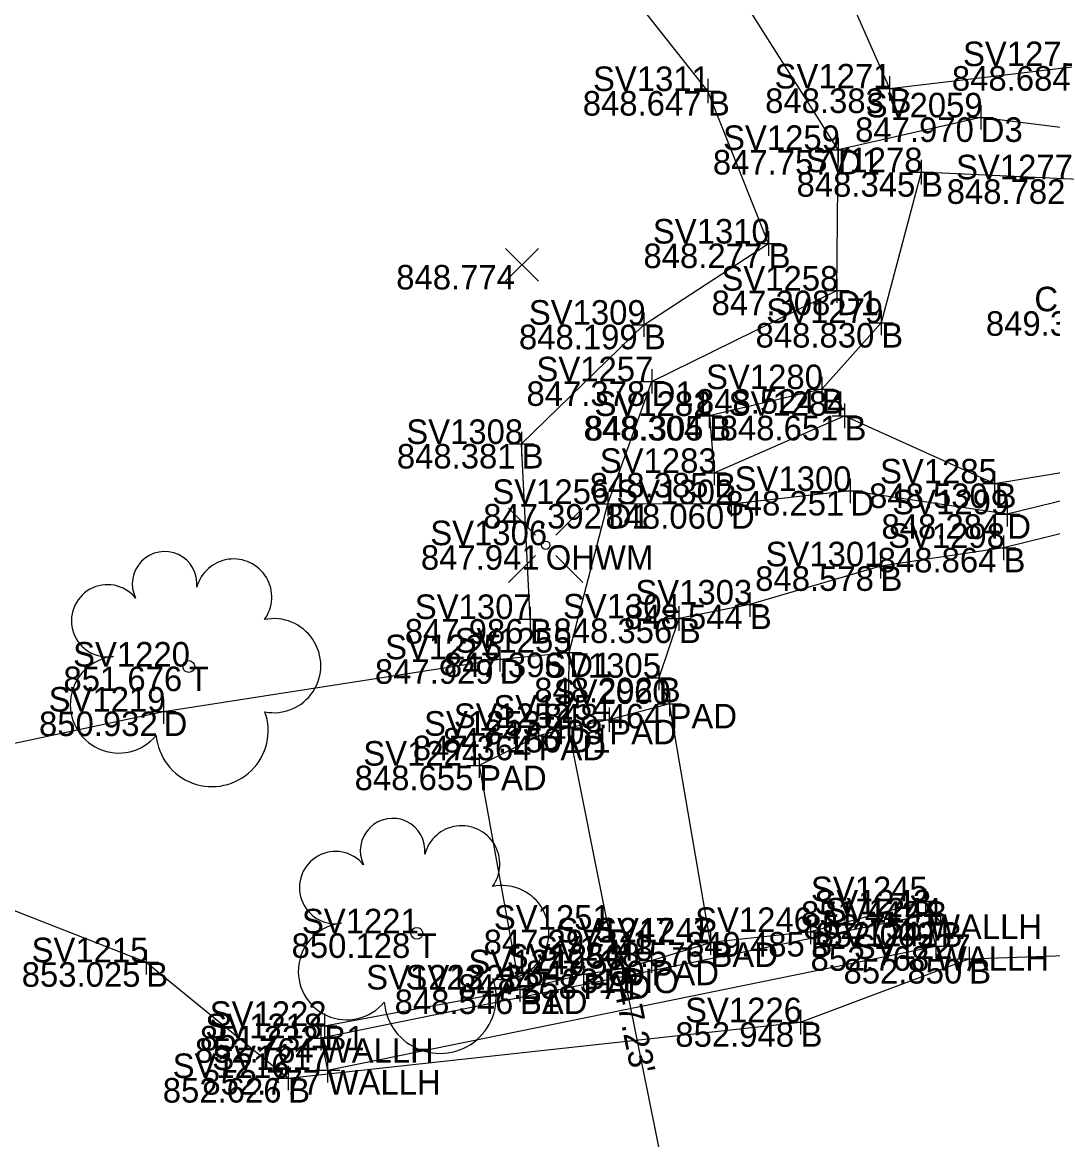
# Model space of a CAD drawing. Extents: x 2125299 to 2129212, y 713100 to 714300.
# Drawn here: x 2128258.44 to 2128300.4, y 714146.02 to 714191.52 of the extents above; entities that cross this region are included whole.
import ezdxf

# ---------------------------------------------------------------- set-up
doc = ezdxf.new("R2010")
doc.units = 0
for name, color, linetype in [('DR_X_Ditch', 7, 'Continuous'), ('DR_X_Headwall', 7, 'Continuous'), ('DR_X_Storm_Sewer', 7, 'Continuous'), ('RD_X_Concrete_Pad', 7, 'Continuous'), ('RW_P_Esmt_TMP', 7, 'Continuous'), ('RW_X_CL_100_Cardinal_Points', 7, 'Continuous'), ('RW_X_CL_100_Stations', 7, 'Continuous'), ('RW_X_Esmt_CH', 7, 'Continuous'), ('RW_X_Fee_WL', 7, 'Continuous'), ('SC_Scratch1', 7, 'Continuous'), ('SV_X_Break_Lines', 7, 'Continuous'), ('SV_X_Mon_Cells_Found', 7, 'Continuous'), ('SV_X_Text_Elevation', 7, 'Continuous'), ('SV_X_Text_Name', 7, 'Continuous')]:
    doc.layers.add(name, color=color, linetype=linetype)

msp = doc.modelspace()

# ---------------------------------------------------------------- linework, layer by layer
at = {"layer": 'DR_X_Ditch'}
for points in [[(2128282.878, 714152.985), (2128282.322, 714154.568), (2128280.684, 714162.784), (2128280.715, 714165.854), (2128282.282, 714171.907), (2128284.07, 714176.901), (2128291.608, 714180.596), (2128291.656, 714186.324), (2128287.057, 714193.601), (2128283.052, 714208.887), (2128284.129, 714216.499), (2128286.829, 714221.225)], [(2128315.102, 714185.935), (2128305.895, 714186.59), (2128297.467, 714187.651), (2128291.656, 714186.324)], [(2128404.428, 714186.272), (2128369.06, 714182.378), (2128353.253, 714176.31), (2128345.761, 714173.482), (2128342.574, 714173.517), (2128335.146, 714174.466), (2128320.718, 714174.933), (2128310.69, 714174.47), (2128298.547, 714171.487), (2128292.157, 714172.437), (2128287.299, 714171.899), (2128282.282, 714171.907)], [(2128126.019, 714119.425), (2128165.524, 714127.077), (2128190.466, 714132.501), (2128226.541, 714148.801), (2128253.762, 714161.242), (2128264.195, 714163.453), (2128277.883, 714165.583), (2128280.715, 714165.854)]]:
    msp.add_lwpolyline(points, dxfattribs=at)
at = {"layer": 'DR_X_Headwall'}
msp.add_lwpolyline([(2128270.591, 714150.148), (2128270.869, 714148.851), (2128295.638, 714153.894), (2128295.357, 714155.189)], close=True, dxfattribs=at)
at = {"layer": 'DR_X_Storm_Sewer'}
msp.add_line((2128282.878, 714152.985), (2128337.681, 713883.118), dxfattribs=at)
at = {"layer": 'RD_X_Concrete_Pad'}
msp.add_lwpolyline([(2128284.794, 714163.766), (2128282.342, 714163.12), (2128280.684, 714162.784), (2128279.461, 714162.469), (2128277.044, 714161.25), (2128278.705, 714152.132), (2128281.29, 714152.752), (2128282.878, 714152.985), (2128284.06, 714153.308), (2128286.462, 714154.049)], close=True, dxfattribs=at)
at = {"layer": 'RW_X_CL_100_Cardinal_Points'}
for p, q in [((2128282.878, 714153.485), (2128282.878, 714152.485)), ((2128282.378, 714152.985), (2128283.378, 714152.985)), ((2128282.878, 714152.985), (2128282.878, 714152.985))]:
    msp.add_line(p, q, dxfattribs=at)
at = {"layer": 'RW_X_CL_100_Stations'}
for centre in [(2128265.221, 714165.285), (2128274.506, 714154.419)]:
    msp.add_circle(centre, 0.24, dxfattribs=at)
for centre, radius, start, end in [((2128264.237, 714168.653), 1.317, 354.0047, 205.9741), ((2128267.047, 714168.114), 1.553, 323.83, 165.0376), ((2128261.912, 714167.149), 1.471, 39.0625, 279.5412), ((2128268.681, 714165.321), 1.915, 259.1453, 101.4596), ((2128262.368, 714163.737), 1.974, 96.1722, 320.5737), ((2128266.167, 714162.68), 2.284, 184.9476, 19.4572), ((2128273.522, 714157.786), 1.317, 354.0047, 205.9741), ((2128276.332, 714157.248), 1.553, 323.83, 165.0376), ((2128271.197, 714156.283), 1.471, 39.0625, 279.5412), ((2128277.966, 714154.454), 1.915, 259.1453, 101.4596), ((2128271.653, 714152.87), 1.974, 96.1722, 320.5737), ((2128275.452, 714151.813), 2.284, 184.9476, 19.4572)]:
    msp.add_arc(centre, radius, start, end, dxfattribs=at)
at = {"layer": 'SV_X_Break_Lines'}
for p, q in [((2128286.358, 714188.724), (2128286.358, 714188.724)), ((2128288.829, 714182.513), (2128288.829, 714182.513)), ((2128283.748, 714179.208), (2128283.748, 714179.208)), ((2128278.774, 714174.351), (2128278.774, 714174.351)), ((2128279.118, 714167.221), (2128279.118, 714167.221))]:
    msp.add_line(p, q, dxfattribs=at)
for points in [[(2128294.731, 714221.25), (2128286.429, 714216.107), (2128286.307, 714216.085), (2128290.211, 714206.434), (2128289.886, 714198.061), (2128291.79, 714193.305), (2128293.753, 714188.829), (2128301.414, 714189.738), (2128311.099, 714187.98), (2128315.392, 714186.993), (2128315.738, 714184.367), (2128308.586, 714184.286), (2128301.154, 714185.129), (2128295.038, 714185.419), (2128293.414, 714179.277), (2128290.994, 714176.583), (2128286.414, 714175.49), (2128286.417, 714175.493), (2128286.617, 714173.173), (2128291.92, 714175.499), (2128298.034, 714172.742), (2128324.661, 714177.129), (2128340.162, 714175.773), (2128345.323, 714175.683)], [(2128279.118, 714167.221), (2128278.774, 714174.351), (2128283.748, 714179.208), (2128288.829, 714182.513), (2128286.358, 714188.724), (2128281.871, 714194.398)], [(2128257.59, 714155.557), (2128263.487, 714153.243), (2128269.265, 714148.527), (2128290.131, 714150.799), (2128296.994, 714153.375), (2128311.857, 714153.897), (2128347.24, 714163.065), (2128380.908, 714169.426), (2128405.403, 714183.348)], [(2128342.539, 714171.803), (2128334.728, 714172.648), (2128320.995, 714173.612), (2128310.963, 714173.215), (2128298.394, 714170.12), (2128293.384, 714169.367), (2128288.065, 714167.811), (2128285.175, 714167.243), (2128284.357, 714164.829), (2128284.794, 714163.766)], [(2128295.832, 714154.861), (2128295.22, 714155.73), (2128290.538, 714154.475), (2128286.462, 714154.049)], [(2128270.743, 714150.65), (2128278.705, 714152.132)]]:
    msp.add_lwpolyline(points, dxfattribs=at)
at = {"layer": 'SV_X_Mon_Cells_Found'}
for p, q in [((2128286.358, 714189.224), (2128286.358, 714188.224)), ((2128293.753, 714189.329), (2128293.753, 714188.329)), ((2128285.858, 714188.724), (2128286.858, 714188.724)), ((2128286.358, 714188.724), (2128286.358, 714188.724)), ((2128293.253, 714188.829), (2128294.253, 714188.829)), ((2128293.753, 714188.829), (2128293.753, 714188.829)), ((2128297.467, 714188.151), (2128297.467, 714187.151)), ((2128296.967, 714187.651), (2128297.967, 714187.651)), ((2128297.467, 714187.651), (2128297.467, 714187.651)), ((2128291.656, 714186.824), (2128291.656, 714185.824)), ((2128291.156, 714186.324), (2128292.156, 714186.324)), ((2128291.656, 714186.324), (2128291.656, 714186.324)), ((2128295.038, 714185.919), (2128295.038, 714184.919)), ((2128294.538, 714185.419), (2128295.538, 714185.419)), ((2128295.038, 714185.419), (2128295.038, 714185.419)), ((2128288.829, 714183.013), (2128288.829, 714182.013)), ((2128288.329, 714182.513), (2128289.329, 714182.513)), ((2128288.829, 714182.513), (2128288.829, 714182.513)), ((2128291.608, 714181.096), (2128291.608, 714180.096)), ((2128291.108, 714180.596), (2128292.108, 714180.596)), ((2128291.608, 714180.596), (2128291.608, 714180.596)), ((2128283.748, 714179.708), (2128283.748, 714178.708)), ((2128293.414, 714179.777), (2128293.414, 714178.777)), ((2128283.248, 714179.208), (2128284.248, 714179.208)), ((2128283.748, 714179.208), (2128283.748, 714179.208)), ((2128292.914, 714179.277), (2128293.914, 714179.277)), ((2128293.414, 714179.277), (2128293.414, 714179.277)), ((2128284.07, 714177.401), (2128284.07, 714176.401)), ((2128283.57, 714176.901), (2128284.57, 714176.901)), ((2128284.07, 714176.901), (2128284.07, 714176.901)), ((2128290.994, 714177.083), (2128290.994, 714176.083)), ((2128290.494, 714176.583), (2128291.494, 714176.583)), ((2128290.994, 714176.583), (2128290.994, 714176.583)), ((2128286.414, 714175.99), (2128286.414, 714174.99)), ((2128286.417, 714175.993), (2128286.417, 714174.993)), ((2128291.92, 714175.999), (2128291.92, 714174.999)), ((2128285.914, 714175.49), (2128286.914, 714175.49)), ((2128285.917, 714175.493), (2128286.917, 714175.493)), ((2128286.414, 714175.49), (2128286.414, 714175.49)), ((2128286.417, 714175.493), (2128286.417, 714175.493)), ((2128291.42, 714175.499), (2128292.42, 714175.499)), ((2128291.92, 714175.499), (2128291.92, 714175.499)), ((2128278.774, 714174.851), (2128278.774, 714173.851)), ((2128278.274, 714174.351), (2128279.274, 714174.351)), ((2128278.774, 714174.351), (2128278.774, 714174.351)), ((2128286.617, 714173.673), (2128286.617, 714172.673)), ((2128286.117, 714173.173), (2128287.117, 714173.173)), ((2128286.617, 714173.173), (2128286.617, 714173.173)), ((2128298.034, 714173.242), (2128298.034, 714172.242)), ((2128292.157, 714172.937), (2128292.157, 714171.937)), ((2128297.534, 714172.742), (2128298.534, 714172.742)), ((2128298.034, 714172.742), (2128298.034, 714172.742)), ((2128282.282, 714172.407), (2128282.282, 714171.407)), ((2128287.299, 714172.399), (2128287.299, 714171.399)), ((2128291.657, 714172.437), (2128292.657, 714172.437)), ((2128292.157, 714172.437), (2128292.157, 714172.437)), ((2128281.782, 714171.907), (2128282.782, 714171.907)), ((2128282.282, 714171.907), (2128282.282, 714171.907)), ((2128286.799, 714171.899), (2128287.799, 714171.899)), ((2128287.299, 714171.899), (2128287.299, 714171.899)), ((2128298.547, 714171.987), (2128298.547, 714170.987)), ((2128298.047, 714171.487), (2128299.047, 714171.487)), ((2128298.547, 714171.487), (2128298.547, 714171.487)), ((2128298.394, 714170.62), (2128298.394, 714169.62)), ((2128297.894, 714170.12), (2128298.894, 714170.12)), ((2128298.394, 714170.12), (2128298.394, 714170.12)), ((2128293.384, 714169.867), (2128293.384, 714168.867)), ((2128292.884, 714169.367), (2128293.884, 714169.367)), ((2128293.384, 714169.367), (2128293.384, 714169.367)), ((2128288.065, 714168.311), (2128288.065, 714167.311)), ((2128279.118, 714167.721), (2128279.118, 714166.721)), ((2128285.175, 714167.743), (2128285.175, 714166.743)), ((2128287.565, 714167.811), (2128288.565, 714167.811)), ((2128288.065, 714167.811), (2128288.065, 714167.811)), ((2128284.675, 714167.243), (2128285.675, 714167.243)), ((2128285.175, 714167.243), (2128285.175, 714167.243)), ((2128278.618, 714167.221), (2128279.618, 714167.221)), ((2128279.118, 714167.221), (2128279.118, 714167.221)), ((2128280.715, 714166.354), (2128280.715, 714165.354)), ((2128277.883, 714166.083), (2128277.883, 714165.083)), ((2128277.383, 714165.583), (2128278.383, 714165.583)), ((2128277.883, 714165.583), (2128277.883, 714165.583)), ((2128280.215, 714165.854), (2128281.215, 714165.854)), ((2128280.715, 714165.854), (2128280.715, 714165.854)), ((2128284.357, 714165.329), (2128284.357, 714164.329)), ((2128283.857, 714164.829), (2128284.857, 714164.829)), ((2128284.357, 714164.829), (2128284.357, 714164.829)), ((2128284.794, 714164.266), (2128284.794, 714163.266)), ((2128264.195, 714163.953), (2128264.195, 714162.953)), ((2128282.342, 714163.62), (2128282.342, 714162.62)), ((2128284.294, 714163.766), (2128285.294, 714163.766)), ((2128284.794, 714163.766), (2128284.794, 714163.766)), ((2128263.695, 714163.453), (2128264.695, 714163.453)), ((2128264.195, 714163.453), (2128264.195, 714163.453)), ((2128280.684, 714163.284), (2128280.684, 714162.284)), ((2128279.461, 714162.969), (2128279.461, 714161.969)), ((2128280.184, 714162.784), (2128281.184, 714162.784)), ((2128280.684, 714162.784), (2128280.684, 714162.784)), ((2128281.842, 714163.12), (2128282.842, 714163.12)), ((2128282.342, 714163.12), (2128282.342, 714163.12)), ((2128278.961, 714162.469), (2128279.961, 714162.469)), ((2128279.461, 714162.469), (2128279.461, 714162.469)), ((2128277.044, 714161.75), (2128277.044, 714160.75)), ((2128276.544, 714161.25), (2128277.544, 714161.25)), ((2128277.044, 714161.25), (2128277.044, 714161.25)), ((2128295.22, 714156.23), (2128295.22, 714155.23)), ((2128294.72, 714155.73), (2128295.72, 714155.73)), ((2128295.22, 714155.73), (2128295.22, 714155.73)), ((2128295.357, 714155.689), (2128295.357, 714154.689)), ((2128282.322, 714155.068), (2128282.322, 714154.068)), ((2128290.538, 714154.975), (2128290.538, 714153.975)), ((2128294.857, 714155.189), (2128295.857, 714155.189)), ((2128295.357, 714155.189), (2128295.357, 714155.189)), ((2128295.832, 714155.361), (2128295.832, 714154.361)), ((2128281.822, 714154.568), (2128282.822, 714154.568)), ((2128282.322, 714154.568), (2128282.322, 714154.568)), ((2128286.462, 714154.549), (2128286.462, 714153.549)), ((2128286.462, 714154.549), (2128286.462, 714153.549)), ((2128295.332, 714154.861), (2128296.332, 714154.861)), ((2128295.832, 714154.861), (2128295.832, 714154.861)), ((2128285.962, 714154.049), (2128286.962, 714154.049)), ((2128285.962, 714154.049), (2128286.962, 714154.049)), ((2128286.462, 714154.049), (2128286.462, 714154.049)), ((2128286.462, 714154.049), (2128286.462, 714154.049)), ((2128290.038, 714154.475), (2128291.038, 714154.475)), ((2128290.538, 714154.475), (2128290.538, 714154.475)), ((2128295.638, 714154.394), (2128295.638, 714153.394)), ((2128263.487, 714153.743), (2128263.487, 714152.743)), ((2128284.06, 714153.808), (2128284.06, 714152.808)), ((2128295.138, 714153.894), (2128296.138, 714153.894)), ((2128295.638, 714153.894), (2128295.638, 714153.894)), ((2128296.994, 714153.875), (2128296.994, 714152.875)), ((2128262.987, 714153.243), (2128263.987, 714153.243)), ((2128263.487, 714153.243), (2128263.487, 714153.243)), ((2128281.29, 714153.252), (2128281.29, 714152.252)), ((2128283.56, 714153.308), (2128284.56, 714153.308)), ((2128284.06, 714153.308), (2128284.06, 714153.308)), ((2128296.494, 714153.375), (2128297.494, 714153.375)), ((2128296.994, 714153.375), (2128296.994, 714153.375)), ((2128280.79, 714152.752), (2128281.79, 714152.752)), ((2128281.29, 714152.752), (2128281.29, 714152.752)), ((2128278.705, 714152.632), (2128278.705, 714151.632)), ((2128278.705, 714152.632), (2128278.705, 714151.632)), ((2128278.205, 714152.132), (2128279.205, 714152.132)), ((2128278.205, 714152.132), (2128279.205, 714152.132)), ((2128278.705, 714152.132), (2128278.705, 714152.132)), ((2128278.705, 714152.132), (2128278.705, 714152.132)), ((2128290.131, 714151.299), (2128290.131, 714150.299)), ((2128270.743, 714151.15), (2128270.743, 714150.15)), ((2128270.243, 714150.65), (2128271.243, 714150.65)), ((2128270.591, 714150.648), (2128270.591, 714149.648)), ((2128270.743, 714150.65), (2128270.743, 714150.65)), ((2128289.631, 714150.799), (2128290.631, 714150.799)), ((2128290.131, 714150.799), (2128290.131, 714150.799)), ((2128270.091, 714150.148), (2128271.091, 714150.148)), ((2128270.591, 714150.148), (2128270.591, 714150.148)), ((2128269.265, 714149.027), (2128269.265, 714148.027)), ((2128270.869, 714149.351), (2128270.869, 714148.351)), ((2128270.369, 714148.851), (2128271.369, 714148.851)), ((2128270.869, 714148.851), (2128270.869, 714148.851)), ((2128268.765, 714148.527), (2128269.765, 714148.527)), ((2128269.265, 714148.527), (2128269.265, 714148.527))]:
    msp.add_line(p, q, dxfattribs=at)
at = {"layer": 'SV_X_Text_Elevation'}
for p, q in [((2128278.122, 714180.974), (2128279.456, 714182.309)), ((2128278.122, 714182.309), (2128279.456, 714180.974))]:
    msp.add_line(p, q, dxfattribs=at)
at = {"layer": 'SV_X_Text_Name'}
for p, q in [((2128278.244, 714171.731), (2128279.337, 714170.637)), ((2128280.171, 714170.637), (2128281.262, 714171.731)), ((2128278.244, 714168.713), (2128279.337, 714169.806)), ((2128280.171, 714169.806), (2128281.262, 714168.713))]:
    msp.add_line(p, q, dxfattribs=at)
msp.add_circle((2128279.754, 714170.227), 0.17, dxfattribs=at)

# ---------------------------------------------------------------- texts
at = {"layer": 'RW_P_Esmt_TMP'}
for s, p in [('B', (2128286.358, 714187.724)), ('B', (2128293.753, 714187.829)), ('D3', (2128297.467, 714186.651)), ('D1', (2128291.656, 714185.324)), ('B', (2128295.038, 714184.419)), ('B', (2128288.829, 714181.513)), ('D1', (2128291.608, 714179.596)), ('B', (2128283.748, 714178.208)), ('B', (2128293.414, 714178.277)), ('D1', (2128284.07, 714175.901)), ('B', (2128290.994, 714175.583)), ('B', (2128286.414, 714174.49)), ('B', (2128286.417, 714174.493)), ('B', (2128291.92, 714174.499)), ('B', (2128278.774, 714173.351)), ('B', (2128286.617, 714172.173)), ('B', (2128298.034, 714171.742)), ('D', (2128292.157, 714171.437)), ('D1', (2128282.282, 714170.907)), ('D', (2128287.299, 714170.899)), ('D', (2128298.547, 714170.487)), ('OHWM', (2128279.754, 714169.227)), ('B', (2128298.394, 714169.12)), ('B', (2128293.384, 714168.367)), ('B', (2128288.065, 714166.811)), ('B', (2128285.175, 714166.243)), ('B', (2128279.118, 714166.221)), ('D', (2128277.883, 714164.583)), ('D1', (2128280.715, 714164.854)), ('T', (2128265.221, 714164.285)), ('B', (2128284.357, 714163.829)), ('PAD', (2128284.794, 714162.766)), ('D', (2128264.195, 714162.453)), ('D1', (2128280.684, 714161.784)), ('PAD', (2128282.342, 714162.12)), ('PAD', (2128279.461, 714161.469)), ('PAD', (2128277.044, 714160.25)), ('B', (2128295.22, 714154.73)), ('WALLH', (2128295.357, 714154.189)), ('D1', (2128282.322, 714153.568)), ('B', (2128295.832, 714153.861)), ('T', (2128274.506, 714153.419)), ('B', (2128286.462, 714153.049)), ('PAD', (2128286.462, 714153.049)), ('B', (2128290.538, 714153.475)), ('WALLH', (2128295.638, 714152.894)), ('B', (2128263.487, 714152.243)), ('PAD', (2128284.06, 714152.308)), ('B', (2128296.994, 714152.375)), ('PAD', (2128281.29, 714151.752)), ('PIO', (2128282.878, 714151.985)), ('B1', (2128278.705, 714151.132)), ('PAD', (2128278.705, 714151.132)), ('B1', (2128270.743, 714149.65)), ('B', (2128290.131, 714149.799)), ('WALLH', (2128270.591, 714149.148)), ('WALLH', (2128270.869, 714147.851)), ('B', (2128269.265, 714147.527))]:
    msp.add_text(s, height=1, dxfattribs=at).set_placement(p)
at = {"layer": 'RW_X_Esmt_CH'}
for s, p in [('SV1272', (2128296.743, 714189.738)), ('SV1311', (2128281.678, 714188.724)), ('SV1271', (2128289.073, 714188.829)), ('SV2059', (2128292.785, 714187.651)), ('SV1259', (2128286.974, 714186.324)), ('SV1278', (2128290.339, 714185.419)), ('SV1277', (2128296.46, 714185.129)), ('SV1310', (2128284.117, 714182.513)), ('SV1258', (2128286.909, 714180.596)), ('CP11', (2128299.651, 714179.755)), ('SV1309', (2128279.066, 714179.208)), ('SV1279', (2128288.732, 714179.277)), ('SV1257', (2128279.376, 714176.901)), ('SV1280', (2128286.282, 714176.583)), ('SV1281', (2128281.734, 714175.49)), ('SV1282', (2128281.746, 714175.493)), ('SV1284', (2128287.2, 714175.499)), ('SV1308', (2128274.075, 714174.351)), ('SV1283', (2128281.955, 714173.173)), ('SV1285', (2128293.365, 714172.742)), ('SV1300', (2128287.445, 714172.437)), ('SV1256', (2128277.58, 714171.907)), ('SV1302', (2128282.628, 714171.899)), ('SV1299', (2128293.865, 714171.487)), ('SV1306', (2128275.052, 714170.227)), ('SV1298', (2128293.695, 714170.12)), ('SV1301', (2128288.704, 714169.367)), ('SV1303', (2128283.403, 714167.811)), ('SV1307', (2128274.424, 714167.221)), ('SV1304', (2128280.455, 714167.243)), ('SV1255', (2128276.046, 714165.854)), ('SV1225', (2128273.214, 714165.583)), ('SV1220', (2128260.509, 714165.285)), ('SV1305', (2128279.688, 714164.829)), ('SV2060', (2128280.082, 714163.766)), ('SV1219', (2128259.513, 714163.453)), ('SV1254', (2128277.622, 714163.12)), ('SV1252', (2128276.013, 714162.784)), ('SV1253', (2128274.799, 714162.469)), ('SV1224', (2128272.324, 714161.25)), ('SV1245', (2128290.551, 714155.73)), ('SV1243', (2128290.695, 714155.189)), ('SV1244', (2128291.112, 714154.861)), ('SV1221', (2128269.826, 714154.419)), ('SV1251', (2128277.642, 714154.568)), ('SV1246', (2128285.836, 714154.475)), ('SV1247_1', (2128280.199, 714154.049)), ('SV1247', (2128281.768, 714154.049)), ('SV1242', (2128290.967, 714153.894)), ('SV1215', (2128258.818, 714153.243)), ('SV1248', (2128279.361, 714153.308)), ('SV1227', (2128292.3, 714153.375)), ('SV1249', (2128276.608, 714152.752)), ('SV1250', (2128278.166, 714152.985)), ('SV1223_1', (2128272.442, 714152.132)), ('SV1223', (2128274.043, 714152.132)), ('SV1226', (2128285.429, 714150.799)), ('SV1222', (2128266.072, 714150.65)), ('SV1218', (2128265.892, 714150.148)), ('SV1216', (2128264.563, 714148.527)), ('SV1217', (2128266.175, 714148.851))]:
    msp.add_text(s, height=1, dxfattribs=at).set_placement(p)
at = {"layer": 'RW_X_Fee_WL'}
for s, p in [('848.684', (2128296.292, 714188.738)), ('848.647', (2128281.262, 714187.724)), ('848.383', (2128288.689, 714187.829)), ('847.970', (2128292.353, 714186.651)), ('847.757', (2128286.56, 714185.324)), ('848.345', (2128289.968, 714184.419)), ('848.782', (2128296.081, 714184.129)), ('848.277', (2128283.733, 714181.513)), ('848.774', (2128273.667, 714180.642)), ('847.308', (2128286.508, 714179.596)), ('849.364', (2128297.676, 714178.755)), ('848.199', (2128278.664, 714178.208)), ('848.830', (2128288.3, 714178.277)), ('847.378', (2128278.97, 714175.901)), ('848.524', (2128285.872, 714175.583)), ('848.304', (2128281.295, 714174.493)), ('848.305', (2128281.344, 714174.49)), ('848.651', (2128286.838, 714174.499)), ('848.381', (2128273.692, 714173.351)), ('848.385', (2128281.547, 714172.173)), ('848.530', (2128292.92, 714171.742)), ('848.251', (2128287.075, 714171.437)), ('847.392', (2128277.209, 714170.907)), ('848.060', (2128282.185, 714170.899)), ('848.284', (2128293.425, 714170.487)), ('847.941', (2128274.672, 714169.227)), ('848.864', (2128293.272, 714169.12)), ('848.578', (2128288.284, 714168.367)), ('848.544', (2128282.943, 714166.811)), ('847.986', (2128274.014, 714166.221)), ('848.356', (2128280.071, 714166.243)), ('847.396', (2128275.611, 714164.854)), ('847.929', (2128272.799, 714164.583)), ('851.676', (2128260.117, 714164.285)), ('848.292', (2128279.284, 714163.829)), ('848.464', (2128279.672, 714162.766)), ('850.932', (2128259.122, 714162.453)), ('847.408', (2128277.242, 714162.12)), ('847.150', (2128275.57, 714161.784)), ('847.364', (2128274.339, 714161.469)), ('848.655', (2128271.974, 714160.25)), ('851.442', (2128290.147, 714154.73)), ('852.756', (2128290.253, 714154.189)), ('847.297', (2128277.226, 714153.568)), ('849.485', (2128285.468, 714153.475)), ('852.009', (2128290.748, 714153.861)), ('850.128', (2128269.406, 714153.419)), ('848.576', (2128281.358, 714153.049)), ('848.576', (2128281.358, 714153.049)), ('852.768', (2128290.538, 714152.894)), ('853.025', (2128258.417, 714152.243)), ('847.200', (2128278.946, 714152.308)), ('852.850', (2128291.88, 714152.375)), ('847.258', (2128276.19, 714151.752)), ('847.231', (2128277.796, 714151.985)), ('848.546', (2128273.601, 714151.132)), ('848.546', (2128273.601, 714151.132)), ('851.232', (2128265.67, 714149.65)), ('852.948', (2128285.031, 714149.799)), ('852.764', (2128265.469, 714149.148)), ('852.777', (2128265.773, 714147.851)), ('852.626', (2128264.161, 714147.527))]:
    msp.add_text(s, height=1, dxfattribs=at).set_placement(p)
at = {"layer": 'SC_Scratch1'}
msp.add_text("847.23'", height=1, rotation=281.4792, dxfattribs=at).set_placement((2128282.388, 714152.886))

doc.saveas('drawing.dxf')
